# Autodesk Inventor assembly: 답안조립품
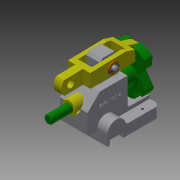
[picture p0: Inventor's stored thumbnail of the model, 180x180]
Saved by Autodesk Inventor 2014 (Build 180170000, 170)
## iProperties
Created: 2016-11
Part Number: 답안조립품
Document SubType Name: Assembly
Designer: USER
Author: USER
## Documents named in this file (8)
- C:\Users\USER\Desktop\461108V1016\답안조립품.iam
- C:\Users\USER\Desktop\461108V1016\본체.ipt
- C:\Users\USER\Desktop\461108V1016\부시.ipt
- C:\Users\USER\Desktop\461108V1016\분할축.ipt
- C:\Users\USER\Desktop\461108V1016\분할대.ipt
- C:\Users\USER\Desktop\461108V1016\와셔.ipt
- C:\Users\USER\Desktop\461108V1016\클레비스핀.ipt
- C:\Users\USER\Desktop\461108V1016\원통형핀.ipt
